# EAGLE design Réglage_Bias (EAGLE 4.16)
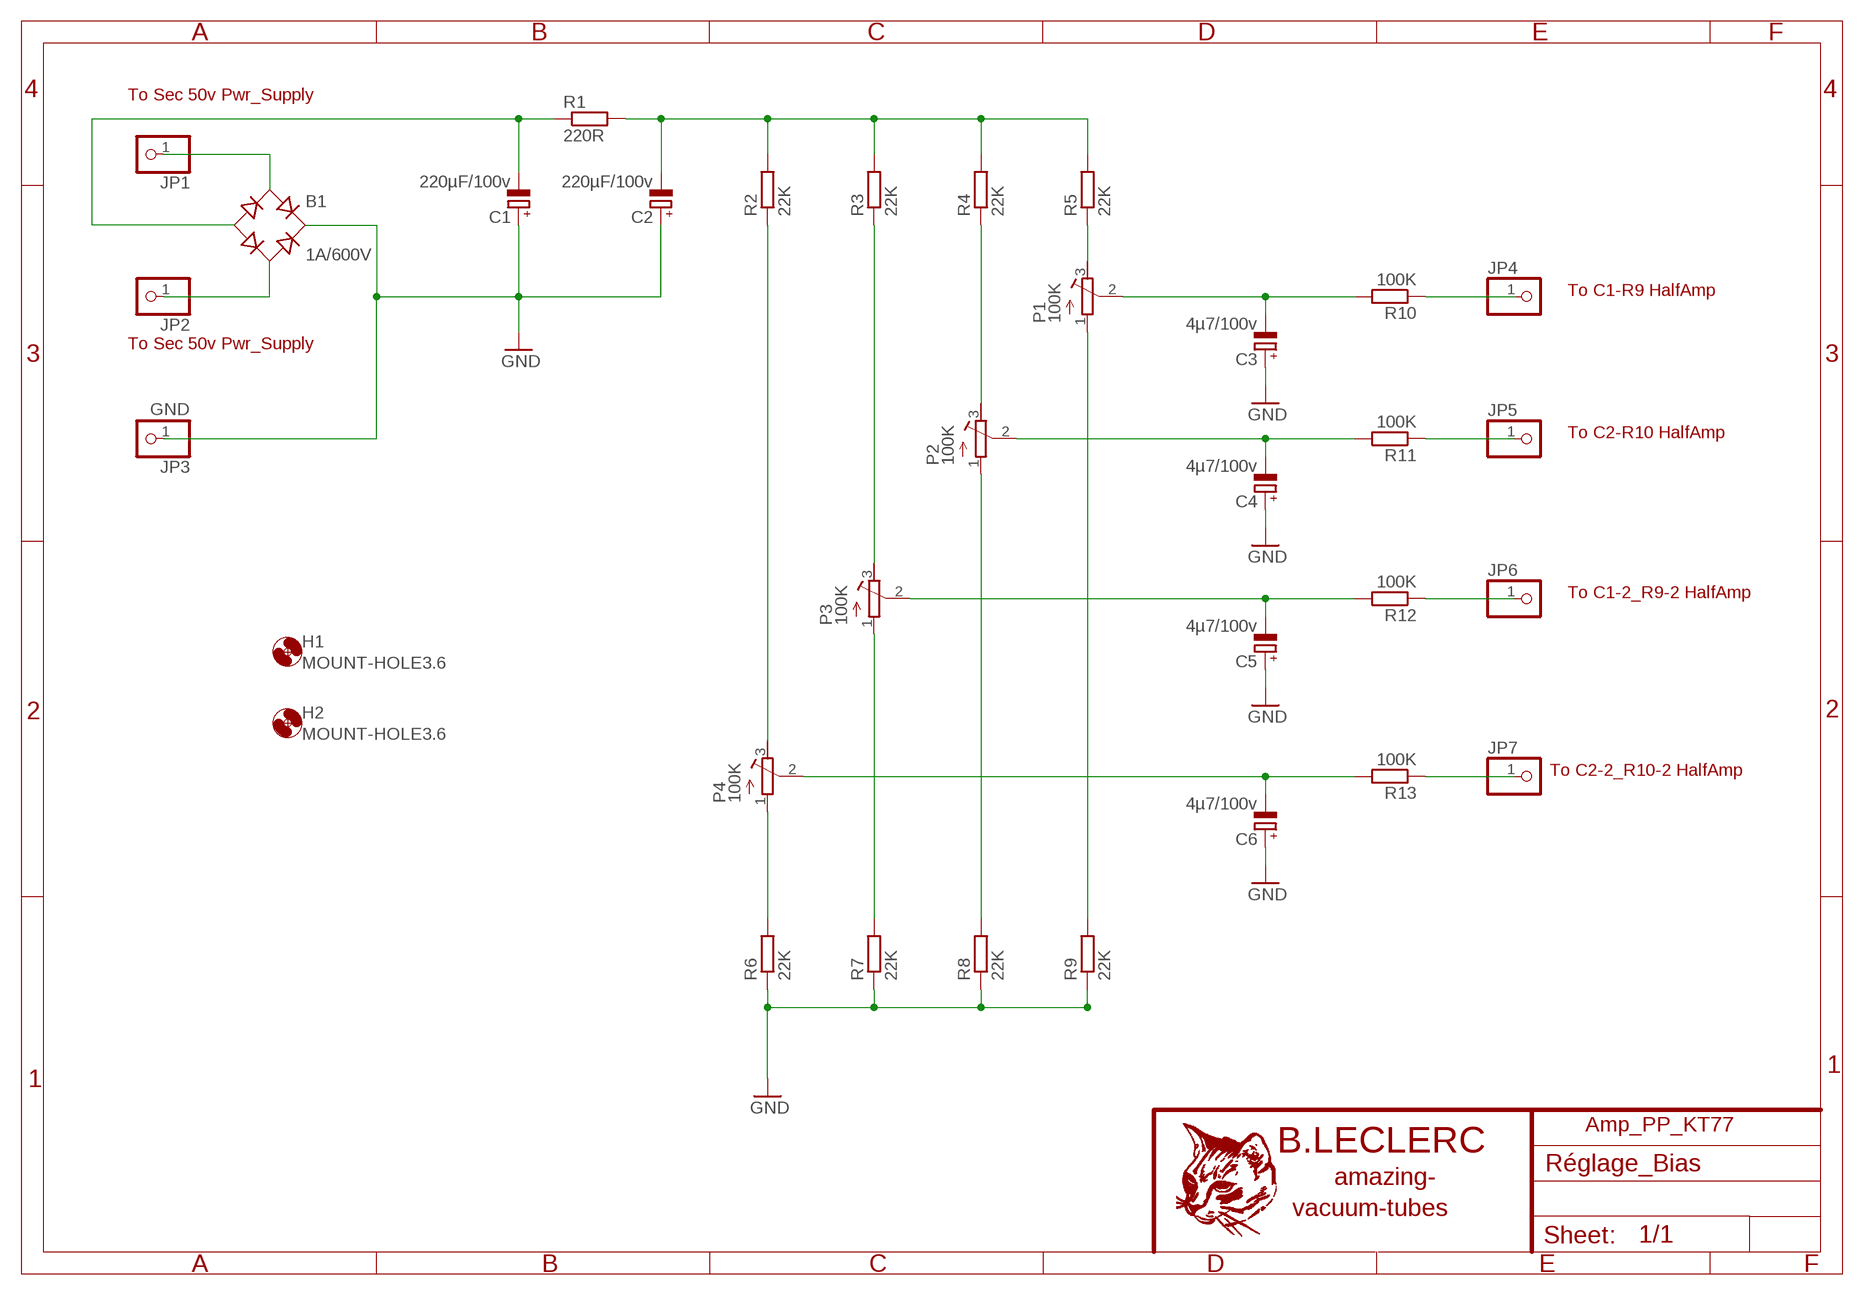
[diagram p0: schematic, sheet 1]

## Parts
B1  1A/600V  RECTIFIER-DIL  [B-DIL]
C1  220µF/100v  CPOL-EUE5-8.5  [E5-8,5]
C2  220µF/100v  CPOL-EUE5-8.5  [E5-8,5]
C3  4µ7/100v  CPOL-EUE2.5-6  [E2,5-6]
C4  4µ7/100v  CPOL-EUE2.5-6  [E2,5-6]
C5  4µ7/100v  CPOL-EUE2.5-6  [E2,5-6]
C6  4µ7/100v  CPOL-EUE2.5-6  [E2,5-6]
H1  MOUNT-HOLE3.6  [3,6]
H2  MOUNT-HOLE3.6  [3,6]
JP1  PINHD-1X1  [1X01]
JP2  PINHD-1X1  [1X01]
JP3  GND  PINHD-1X1  [1X01]
JP4  PINHD-1X1  [1X01]
JP5  PINHD-1X1  [1X01]
JP6  PINHD-1X1  [1X01]
JP7  PINHD-1X1  [1X01]
P1  100K  R-TRIMM64W  [RTRIM64W]
P2  100K  R-TRIMM64W  [RTRIM64W]
P3  100K  R-TRIMM64W  [RTRIM64W]
P4  100K  R-TRIMM64W  [RTRIM64W]
R1  220R  R-EU_0309/12  [0309/12]
R2  22K  R-EU_0309/12  [0309/12]
R3  22K  R-EU_0309/12  [0309/12]
R4  22K  R-EU_0309/12  [0309/12]
R5  22K  R-EU_0309/12  [0309/12]
R6  22K  R-EU_0309/12  [0309/12]
R7  22K  R-EU_0309/12  [0309/12]
R8  22K  R-EU_0309/12  [0309/12]
R9  22K  R-EU_0309/12  [0309/12]
R10  100K  R-EU_0309/12  [0309/12]
R11  100K  R-EU_0309/12  [0309/12]
R12  100K  R-EU_0309/12  [0309/12]
R13  100K  R-EU_0309/12  [0309/12]

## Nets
GND: B1.+ C1.+ C2.+ C3.+ C4.+ C5.+ C6.+ JP3.1 R6.1 R7.1 R8.1 R9.1
N$1: B1.AC1 JP1.1
N$2: B1.AC2 JP2.1
N$3: P1.3(A) R5.1
N$4: B1.- C1.- R1.1
N$5: C2.- R1.2 R2.2 R3.2 R4.2 R5.2
N$6: P2.3(A) R4.1
N$7: P3.3(A) R3.1
N$8: P4.3(A) R2.1
N$9: P4.1(E) R6.2
N$10: P3.1(E) R7.2
N$11: P2.1(E) R8.2
N$12: P1.1(E) R9.2
N$13: C3.- P1.2(S) R10.2
N$14: C4.- P2.2(S) R11.2
N$15: C5.- P3.2(S) R12.2
N$16: C6.- P4.2(S) R13.2
N$17: JP4.1 R10.1
N$18: JP5.1 R11.1
N$19: JP6.1 R12.1
N$20: JP7.1 R13.1

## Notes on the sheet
- To Sec 50v Pwr_Supply
- To C1-R9 HalfAmp
- To Sec 50v Pwr_Supply
- To C2-R10 HalfAmp
- To C1-2_R9-2 HalfAmp
- To C2-2_R10-2 HalfAmp
- Amp_PP_KT77

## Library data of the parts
B1 = rectifier:RECTIFIER-: Rectifier
C1-C6 = rcl:CPOL-EU: POLARIZED CAPACITOR, European symbol
H1 H2 = holes:MOUNT-HOLE: MOUNTING HOLE with drill center marker
JP1-JP7 = pinhead:PINHD-1X1: PIN HEADER
P1-P4 = rcl:R-TRIMM: Trimm resistor
R1-R13 = rcl:R-EU_: RESISTOR, European symbol

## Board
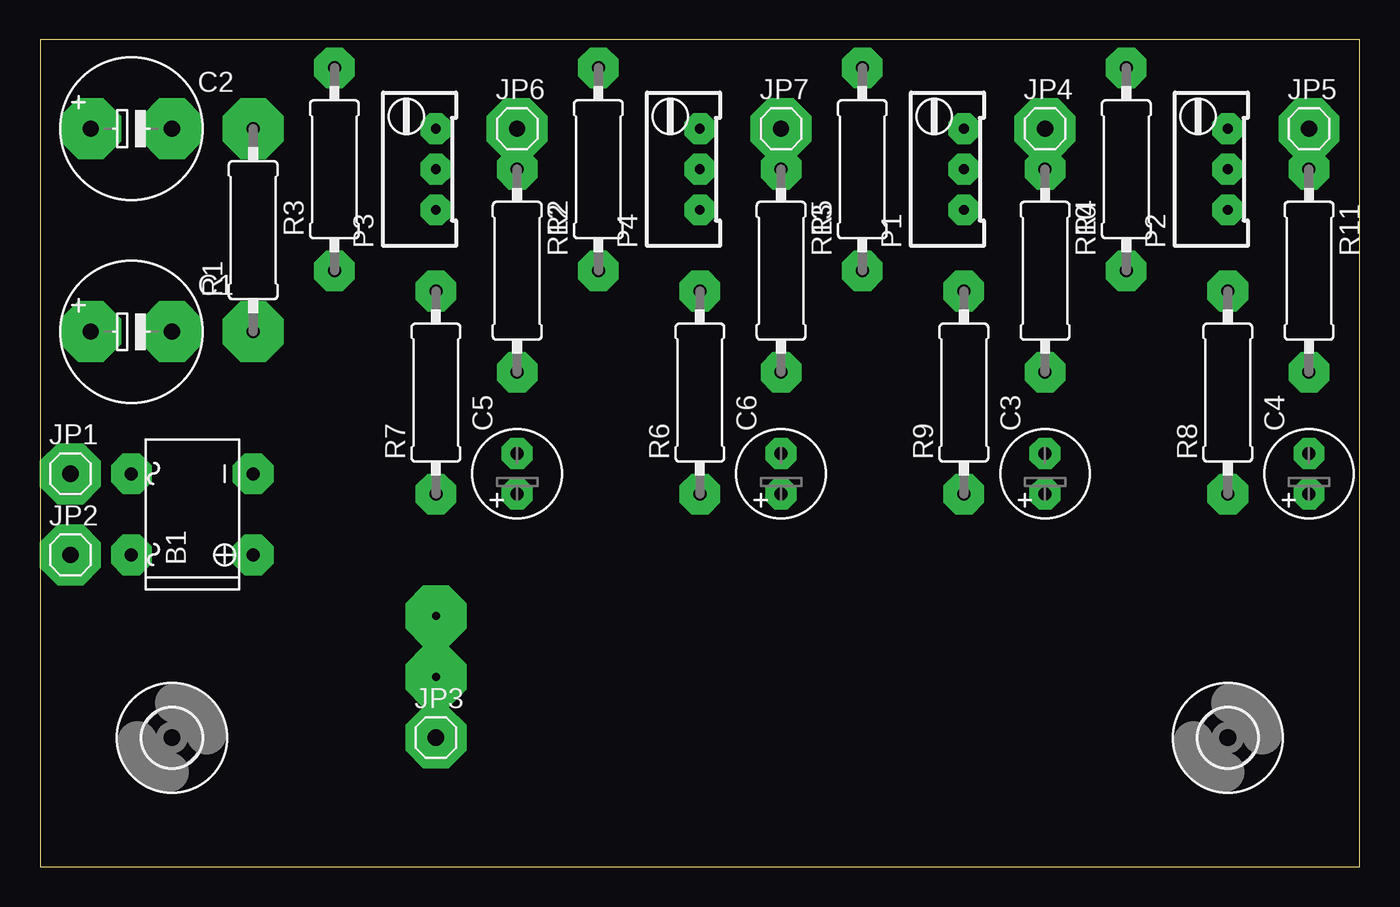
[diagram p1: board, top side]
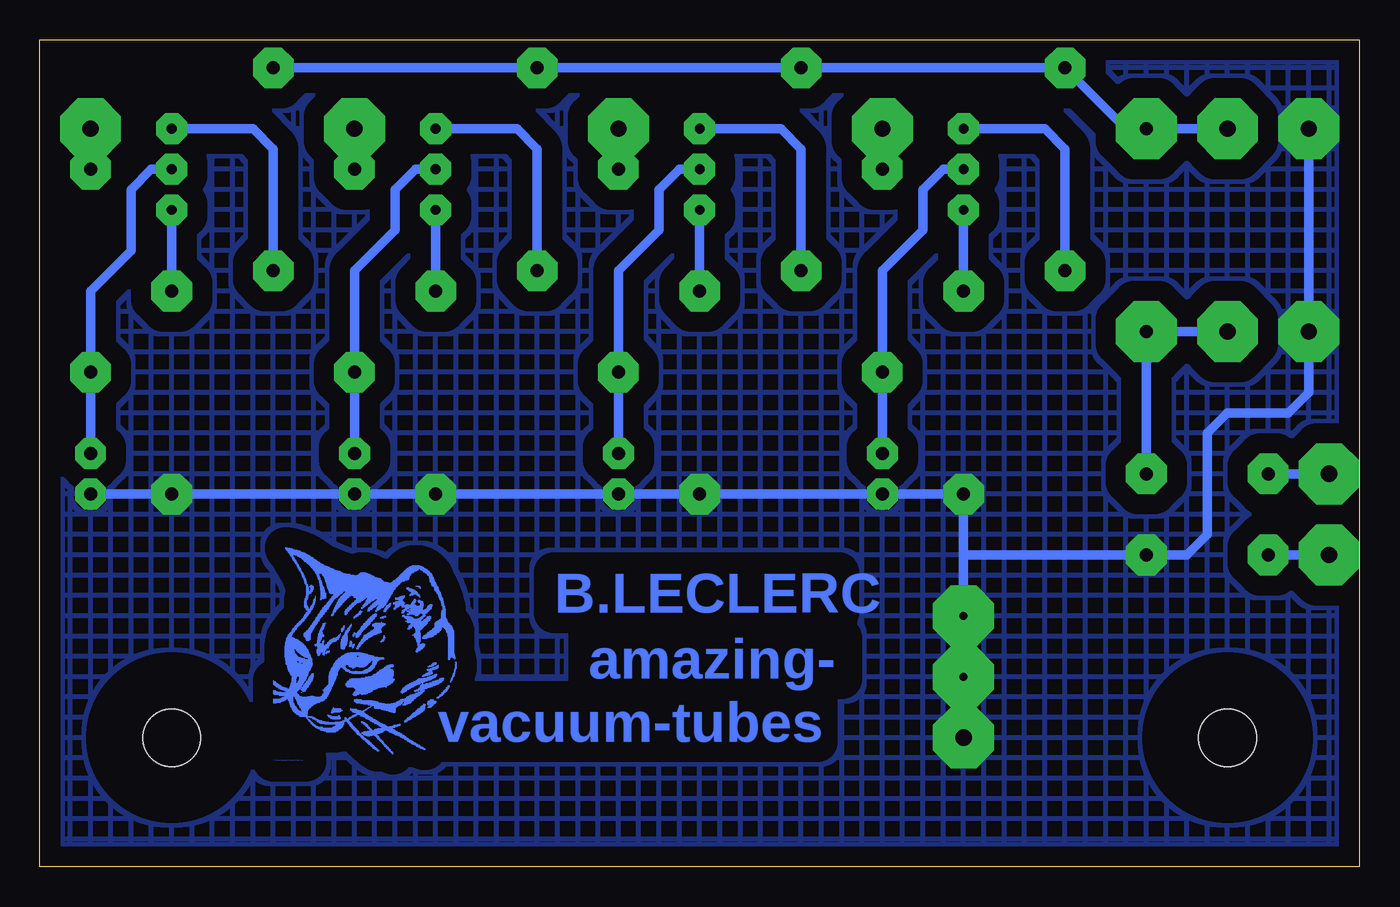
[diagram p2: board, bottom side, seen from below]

Size 82.53 x 51.74 mm. Coordinates in mm from the lower left corner, seen from the top.
Outline: 0,0 82.53,0 82.53,51.74 0,51.74 0,0
Copper layers (1*16): Top 0.035mm / dielectric 1.5mm / Bottom 0.035mm
Design rules "default": minimum track width 10mil, minimum drill 24mil, track to track 8mil, track to pad 8mil, pad to pad 8mil, via to via 8mil, smd to smd 8mil, copper to edge 40mil, drill to drill 8mil, minimum pad ring 10mil, minimum via ring 8mil, stop-mask expansion 4mil, vias tented up to drill 0mil, thermal gap 10mil

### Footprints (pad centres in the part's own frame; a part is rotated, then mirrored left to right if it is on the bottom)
B-DIL = drill 0.813 round: + -2.54,-3.81 | drill 0.813 octagon: - 2.54,-3.81; AC1 2.54,3.81; AC2 -2.54,3.81
E5-8,5 = drill 1.016 pad 2.54 round: + -2.54,0 | drill 1.016 pad 2.54 octagon: - 2.54,0
E2,5-6 = drill 0.813 pad 1.6 round: + -1.27,0 | drill 0.813 pad 1.6 octagon: - 1.27,0
3,6 = hole 3.6: 0,0
1X01 = drill 1.016 octagon: 1 0,0
RTRIM64W = drill 0.61 round: 1 1.27,-2.54; 2 1.27,0; 3 1.27,2.54
0309/12 = drill 0.813 octagon: 1 -6.35,0; 2 6.35,0

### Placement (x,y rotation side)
B1  9.52,22.06 90 top
C1  22µF/100v  [E5-8,5]  5.71,33.49 0 top
C2  22µF/100v  [E5-8,5]  5.71,46.19 0 top
C3  62.86,24.6 90 top
C4  79.37,24.6 90 top
C5  29.84,24.6 90 top
C6  46.35,24.6 90 top
H1  8.25,8.09 0 top
H2  74.29,8.09 0 top
JP1  1.9,24.6 0 top
JP2  1.9,19.52 0 top
JP3  24.76,8.09 0 top
JP4  62.86,46.19 0 top
JP5  79.37,46.19 0 top
JP6  29.84,46.19 0 top
JP7  46.35,46.19 0 top
P1  56.51,43.65 0 top
P2  73.02,43.65 0 top
P3  23.49,43.65 0 top
P4  40,43.65 0 top
R1  13.33,39.84 90 top
R2  34.92,43.65 90 top
R3  18.41,43.65 90 top
R4  67.94,43.65 90 top
R5  51.43,43.65 90 top
R6  41.27,29.68 90 top
R7  24.76,29.68 90 top
R8  74.29,29.68 90 top
R9  57.78,29.68 90 top
R10  62.86,37.3 270 top
R11  79.37,37.3 270 top
R12  29.84,37.3 270 top
R13  46.35,37.3 270 top
U$3  [CHAT1]  67.94,6.82 0 bottom

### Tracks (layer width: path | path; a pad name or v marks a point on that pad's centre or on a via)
GND  (via drill 0.5 pad 1.93, 0.5 pad 2.54, 0.5 pad 3.81)
  Bottom 0.61: C2.+ C1.+ 3.17,29.68 4.44,28.41 8.25,28.41 9.52,27.14 9.52,20.79 10.79,19.52 B1.+ 24.76,19.52 | C4.+ R8.1 C3.+ R9.1 C6.+ R6.1 C5.+ R7.1 24.76,19.52 | 24.76,19.52 JP3.1
  other vias: 13.33,19.52 24.76,8.09 24.76,11.9 24.76,15.71 3.17,46.19 3.17,33.49 24.76,23.33 29.84,23.33 41.27,23.33 46.35,23.33 57.78,23.33 62.86,23.33 74.29,23.33 79.37,23.33
  pour Bottom (isolate 1.27, hatched): 0.63,51.27 81.91,51.27 81.91,0.47 0.63,0.47
N$1
  Bottom 0.61: JP1.1 B1.AC1
N$2
  Bottom 0.61: JP2.1 B1.AC2
N$3
  Bottom 0.61: P1.3 52.7,46.19 51.43,44.92 R5.1
N$4
  Bottom 0.61: B1.- R1.1 C1.-
N$5
  Bottom 0.61: C2.- R1.2 14.6,46.19 R3.2 R2.2 R5.2 R4.2
N$6
  Bottom 0.61: P2.3 69.21,46.19 67.94,44.92 R4.1
N$7
  Bottom 0.61: P3.3 19.68,46.19 18.41,44.92 R3.1
N$8
  Bottom 0.61: P4.3 36.19,46.19 34.92,44.92 R2.1
N$9
  Bottom 0.61: R6.2 P4.1
N$10
  Bottom 0.61: R7.2 P3.1
N$11
  Bottom 0.61: R8.2 P2.1
N$12
  Bottom 0.61: R9.2 P1.1
N$13
  Bottom 0.61: P1.2 59.05,43.65 60.32,42.38 60.32,39.84 62.86,37.3 R10.2 C3.-
N$14
  Bottom 0.61: P2.2 75.56,43.65 76.83,42.38 76.83,38.57 79.37,36.03 R11.2 C4.-
N$15
  Bottom 0.61: P3.2 26.03,43.65 27.3,42.38 27.3,39.84 29.84,37.3 R12.2 C5.-
N$16
  Bottom 0.61: P4.2 42.54,43.65 43.81,42.38 43.81,39.84 46.35,37.3 R13.2 C6.-
N$17
  Bottom 0.61: R10.1 JP4.1
N$18
  Bottom 0.61: R11.1 JP5.1
N$19
  Bottom 0.61: R12.1 JP6.1
N$20
  Bottom 0.61: R13.1 JP7.1
N$21  (via drill 0.5 pad 3.81)
  other vias: 79.37,46.19
N$22  (via drill 0.5 pad 3.81)
  other vias: 62.86,46.19
N$23  (via drill 0.5 pad 3.81)
  other vias: 46.35,46.19
N$24  (via drill 0.5 pad 3.81)
  other vias: 13.33,33.49
N$25  (via drill 0.5 pad 3.81)
  other vias: 29.84,46.19
N$26  (via drill 0.5 pad 3.81)
  other vias: 8.25,46.19
N$29  (via drill 0.5 pad 3.81)
  other vias: 13.33,46.19
N$30  (via drill 0.5 pad 3.81)
  other vias: 8.25,33.49
N$34  (via drill 0.5 pad 3.81)
  other vias: 1.9,19.52
N$35  (via drill 0.5 pad 3.81)
  other vias: 1.9,24.6
N$36  (via drill 0.5 pad 2.54)
  other vias: 18.41,37.3
N$37  (via drill 0.5 pad 2.54)
  other vias: 62.86,43.65
N$38  (via drill 0.5 pad 2.54)
  other vias: 79.37,43.65
N$39  (via drill 0.5 pad 2.54)
  other vias: 29.84,30.95
N$40  (via drill 0.5 pad 2.54)
  other vias: 46.35,30.95
N$41  (via drill 0.5 pad 2.54)
  other vias: 62.86,30.95
N$42  (via drill 0.5 pad 2.54)
  other vias: 18.41,50
N$43  (via drill 0.5 pad 2.54)
  other vias: 67.94,50
N$44  (via drill 0.5 pad 2.54)
  other vias: 51.43,50
N$45  (via drill 0.5 pad 2.54)
  other vias: 34.92,50
N$46  (via drill 0.5 pad 2.54)
  other vias: 46.35,43.65
N$47  (via drill 0.5 pad 2.54)
  other vias: 34.92,37.3
N$48  (via drill 0.5 pad 2.54)
  other vias: 51.43,37.3
N$49  (via drill 0.5 pad 2.54)
  other vias: 67.94,37.3
N$50  (via drill 0.5 pad 2.54)
  other vias: 29.84,43.65
N$51  (via drill 0.5 pad 2.54)
  other vias: 79.37,30.95
N$52  (via drill 0.5 pad 1.93)
  other vias: 62.86,25.87
N$53  (via drill 0.5 pad 2.54)
  other vias: 57.78,36.03
N$55  (via drill 0.5 pad 2.54)
  other vias: 41.27,36.03
N$56  (via drill 0.5 pad 1.93)
  other vias: 46.35,25.87
N$57  (via drill 0.5 pad 2.54)
  other vias: 74.29,36.03
N$60  (via drill 0.5 pad 2.54)
  other vias: 24.76,36.03
N$62  (via drill 0.5 pad 1.93)
  other vias: 29.84,25.87
N$63  (via drill 0.5 pad 1.93)
  other vias: 57.78,43.65
N$64  (via drill 0.5 pad 1.93)
  other vias: 41.27,41.11
N$65  (via drill 0.5 pad 1.93)
  other vias: 57.78,46.19
N$66  (via drill 0.5 pad 1.93)
  other vias: 57.78,41.11
N$67  (via drill 0.5 pad 1.93)
  other vias: 74.29,46.19
N$68  (via drill 0.5 pad 1.93)
  other vias: 74.29,43.65
N$69  (via drill 0.5 pad 1.93)
  other vias: 74.29,41.11
N$73  (via drill 0.5 pad 1.93)
  other vias: 79.37,25.87
N$74  (via drill 0.5 pad 2.54)
  other vias: 5.71,19.52
N$76  (via drill 0.5 pad 2.54)
  other vias: 13.33,24.6
N$77  (via drill 0.5 pad 2.54)
  other vias: 5.71,24.6
N$79  (via drill 0.5 pad 1.93)
  other vias: 41.27,43.65
N$80  (via drill 0.5 pad 1.93)
  other vias: 41.27,46.19
N$81  (via drill 0.5 pad 1.93)
  other vias: 24.76,46.19
N$82  (via drill 0.5 pad 1.93)
  other vias: 24.76,41.11
N$83  (via drill 0.5 pad 1.93)
  other vias: 24.76,43.65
